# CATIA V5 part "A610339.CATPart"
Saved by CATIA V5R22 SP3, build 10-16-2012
Part number: D38999/26TH35PN
Revision: A
Definition: A610339
Nomenclature: CONNECTOR, ELEC, PLUG, CIRCULAR, THD, STR, REM CRP CONT
Source: bought
Description: CONNECTOR, ELEC, PLUG, CIRCULAR, THD, STR, REM CRP CONT
Publications: "Logical Termination.1", "Logical Pin.1", "CCP", "CCP_generated(CCP)", "Coincidence_generated(CCP)", "CCP Orientation_generated(CCP)", "BCP", "BCP_generated(BCP)", "Face_generated(BCP)", "BaCP", "BaCP_generated(BaCP)", "BaCP Orientation_generated(BaCP)"
Material "Density=.1010": density 2795.67 kg/m3
Bounding box of the stored display mesh (mm): x -33.16 to 0, y -22.264 to 22.264, z -22.43 to 22.43
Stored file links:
  C:\Users\u305772\OneDrive - Gulfstream Aerospace\AD PAG\Harness\A610339.CATPart
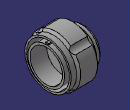
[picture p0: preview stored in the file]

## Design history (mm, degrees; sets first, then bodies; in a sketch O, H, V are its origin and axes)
Parameters
  PartNumber = "D38999/26TH35PN"
  OtherKeywords = "CONNECTORS, ELECTRICAL, PLUG, CIRCULAR, THREADED, STRAIGHT, REMOVABLE CRIMP CONTACTS SERIES III, METRIC"
  Comments = "DD THD: 1.5, VV THD: M34x1.0-6g 0.100R, NICKEL FLUOROCARBON POLYMER OVER A SUITABLE UNDERPLATE (CONDUCTIVE) -65 DEG C TO +175 DEG C, PIN"
  CAGECode = "96906"
  WeightComment = "CALCULATED FROM CATIA"
  WeightSource = "Calculated"
  Volume = 2.82225e-05 (volume) {= smartVolume(Body1)}
  Density = 2795.67 (density)
  Weight = 0.13638
AxisSystem1: origin (0, 0, 0), X (1, 0, 0), Y (0, 1, 0), Z (0, 0, 1)
Set1
  Point1 "CCP": type Center, Curve edge [face of Shaft1 from Sketch1.L2 | face of Shaft1 from Sketch1.L1]
  Point2 "BaCP": type Center, Curve edge [face of Shaft1 from Sketch1.L17 | face of Shaft1 from Sketch1.L16]
  Point3 "BCP": type Center, Curve edge [face of Shaft1 from Sketch1.L19 | face of Shaft1 from Sketch1.L18]
  Point4: (0, 0, 3.175), relative to Point1, in AxisSystem1
  Point5: (0, 0, 3.175), relative to Point2, in AxisSystem1
  Line1 "Coincidence": type PtPt, FirstPoint Point1, SecondPoint Point3
  Line2 "CCP Orientation": type PtPt, FirstPoint Point1, SecondPoint Point4
  Line3 "BaCP Orientation": type PtPt, FirstPoint Point2, SecondPoint Point5
Body1 (main body)
  Sketch1 on ZX plane of AxisSystem1, origin (0, 0, 0), H (1, 0, 0), V (0, 0, 1)
    point P1 (-14.565, 0)
    line L1 (-14.565, 0) -> (-14.565, 14.175)
    point P2 (-14.565, 14.175)
    line L2 (-14.565, 14.175) -> (-15.01, 14.175)
    point P3 (-15.01, 14.175)
    line L3 (-15.01, 14.175) -> (-15.01, 14.385)
    point P4 (-15.01, 14.385)
    line L4 (-15.01, 14.385) -> (0, 14.385)
    point P5 (0, 14.385)
    line L5 (0, 14.385) -> (0, 16.2575)
    point P6 (0, 16.2575)
    line L6 (0, 16.2575) -> (-15.01, 16.2575)
    point P7 (-15.01, 16.2575)
    line L7 (-15.01, 16.2575) -> (-15.01, 19.05)
    point P8 (-15.01, 19.05)
    line L8 (-15.01, 19.05) -> (-1.54, 19.05)
    point P9 (-1.54, 19.05)
    line L9 (-1.54, 19.05) -> (-1.54, 20.55)
    point P10 (-1.54, 20.55)
    line L10 (-1.54, 20.55) -> (-6.24, 20.55)
    point P11 (-6.24, 20.55)
    line L11 (-6.24, 20.55) -> (-8.14, 22.45)
    point P12 (-8.14, 22.45)
    line L12 (-8.14, 22.45) -> (-23, 22.45)
    point P13 (-23, 22.45)
    line L13 (-23, 22.45) -> (-23, 17)
    point P14 (-23, 17)
    line L14 (-23, 17) -> (-27.74, 17)
    point P15 (-27.74, 17)
    line L15 (-27.74, 17) -> (-28.46, 16.28)
    point P16 (-28.46, 16.28)
    line L16 (-28.46, 16.28) -> (-31, 16.28)
    point P17 (-31, 16.28)
    line L17 (-31, 16.28) -> (-31, 14.565)
    point P18 (-31, 14.565)
    line L18 (-31, 14.565) -> (-33.16, 14.565)
    point P19 (-33.16, 14.565)
    line L19 (-33.16, 14.565) -> (-33.16, 0)
    point P20 (-33.16, 0)
    axis line L20 (-33.16, 0) -> (-14.565, 0)
    point P21 (-14.565, -14.175)
    point P22 (-14.565, 0)
    construction line L21 (-14.565, 0) -> (-14.565, -14.175)
    point P23 (-15.01, -14.175)
    construction line L22 (-14.565, -14.175) -> (-15.01, -14.175)
    point P24 (-15.01, -14.385)
    construction line L23 (-15.01, -14.175) -> (-15.01, -14.385)
    point P25 (0, -14.385)
    construction line L24 (-15.01, -14.385) -> (0, -14.385)
    point P26 (0, -16.2575)
    construction line L25 (0, -14.385) -> (0, -16.2575)
    point P27 (-15.01, -16.2575)
    construction line L26 (0, -16.2575) -> (-15.01, -16.2575)
    point P28 (-15.01, -19.05)
    construction line L27 (-15.01, -16.2575) -> (-15.01, -19.05)
    point P29 (-1.54, -19.05)
    construction line L28 (-15.01, -19.05) -> (-1.54, -19.05)
    point P30 (-1.54, -20.55)
    construction line L29 (-1.54, -19.05) -> (-1.54, -20.55)
    point P31 (-6.24, -20.55)
    construction line L30 (-1.54, -20.55) -> (-6.24, -20.55)
    point P32 (-8.14, -22.45)
    construction line L31 (-6.24, -20.55) -> (-8.14, -22.45)
    point P33 (-23, -22.45)
    construction line L32 (-8.14, -22.45) -> (-23, -22.45)
    point P34 (-23, -17)
    construction line L33 (-23, -22.45) -> (-23, -17)
    point P35 (-27.74, -17)
    construction line L34 (-23, -17) -> (-27.74, -17)
    point P36 (-28.46, -16.28)
    construction line L35 (-27.74, -17) -> (-28.46, -16.28)
    point P37 (-31, -16.28)
    construction line L36 (-28.46, -16.28) -> (-31, -16.28)
    point P38 (-31, -14.565)
    construction line L37 (-31, -16.28) -> (-31, -14.565)
    point P39 (-33.16, -14.565)
    construction line L38 (-31, -14.565) -> (-33.16, -14.565)
    point P40 (-33.16, 0)
    construction line L39 (-33.16, -14.565) -> (-33.16, 0)
    distance L9 P11 = 4.7
    distance L10 L30 = 41.1
    distance L12 L32 = 44.9
    distance L5 L17 = 31
    distance L2 L22 = 28.35
    angle L16 L15 = 45
    angle L10 L11 = 45
    distance L5 L7 = 15.01
    distance L6 L26 = 32.515
    distance L24 L4 = 28.77
    distance L3 L1 = 0.445
    distance L8 L28 = 38.1
    distance L7 L9 = 13.47
    distance L17 L13 = 8
    distance L17 L19 = 2.16
    distance L38 L18 = 29.13
    distance L36 L16 = 32.56
    distance L34 L14 = 34
    distance L17 P16 = 2.54
    coincidence: P1 H, P5 V, P20 H, L7 L3
    vertical: L1 V, L3 V, L5 V, L7 V, L9 V, L13 V, L17 V, L19 V
    horizontal: L2 H, L4 H, L6 H, L8 H, L10 H, L12 H, L14 H, L16 H, L18 H, L20 H
    symmetry: P2 P21 L20, P1 P22 L20, L1 L21 L20, P3 P23 L20, L2 L22 L20, P4 P24 L20, L3 L23 L20, P5 P25 L20, L4 L24 L20, P6 P26 L20, L5 L25 L20, P7 P27 L20, L6 L26 L20, P8 P28 L20, L7 L27 L20, P9 P29 L20, L8 L28 L20, P10 P30 L20, L9 L29 L20, P11 P31 L20, L10 L30 L20, P12 P32 L20, L11 L31 L20, P13 P33 L20, L12 L32 L20, P14 P34 L20, L13 L33 L20, P15 P35 L20, L14 L34 L20, P16 P36 L20, L15 L35 L20, P17 P37 L20, L16 L36 L20, P18 P38 L20, L17 L37 L20, P19 P39 L20, L18 L38 L20, P20 P40 L20, L19 L39 L20
  Shaft1: profile Sketch1, axis Sketch1.L20, angle 360
  Sketch2 on face of Shaft1 from Sketch1.L5, origin (0, 0, 0), H (0, 1, 0), V (0, 0, 1)
    construction circle A1 centre (0, 0) radius 20.85
    construction line L1 (-20.85, 0) -> (20.85, 0)
    point P1 (-20.85, 0)
    point P2 (20.85, 0)
    arc A2 centre (17.8223, 17.8223) radius 4.3546 from (13.4699, 17.9601) to (17.9601, 13.4699) ccw
    arc A3 centre (0, 0) radius 22.45 from (17.9601, 13.4699) to (13.4699, 17.9601) ccw
    construction line L2 (0, 0) -> (17.8223, 17.8223)
    reference projected circle E1 centre (0, 0) radius 22.45 from edge [face of Shaft1 from Sketch1.L12 | face of Shaft1 from Sketch1.L11]
    point P4 (17.9601, 13.4699)
    point P5 (13.4699, 17.9601)
    length L1 = 41.7
    angle L1 L2 = 45
    distance P5 P4 = 6.35
    coincidence: P1 A1, P1 H, P2 A1
    horizontal: L1 H
    tangency: A2 A1, A3 E1
  Pocket1: profile Sketch2, direction (-1, 0, 0), through (limit type 6)
  CircPattern1: of Pocket1, instances 4, angular step 90, axis from face of Shaft1 from Sketch1.L9
  Sketch3 on face of Shaft1 from Sketch1.L5, origin (0, 0, 0), H (0, 1, 0), V (0, 0, 1)
    arc A1 centre (0, 0) radius 16.2575 from (1.27, 16.2078) to (-1.27, 16.2078) ccw
    line L1 (1.27, 17.2182) -> (1.27, 16.2078)
    line L2 (-1.27, 16.2078) -> (-1.27, 17.2182)
    point P1 (1.27, 16.2078)
    point P2 (-1.27, 16.2078)
    reference projected circle E1 centre (0, 0) radius 16.2575 from edge [face of Shaft1 from Sketch1.L6 | face of Shaft1 from Sketch1.L5]
    point P3 (-1.27, -16.2078)
    point P4 (1.27, -16.2078)
    construction arc A2 centre (0, 0) radius 16.2575 from (1.27, -16.2078) to (-1.27, -16.2078) cw
    construction line L3 (-1.27, -16.2078) -> (-1.27, -17.2182)
    construction line L4 (1.27, -17.2182) -> (1.27, -16.2078)
    arc A3 centre (0, 0) radius 17.265 from (1.27, 17.2182) to (-1.27, 17.2182) ccw
    point P6 (1.27, 17.2182)
    point P7 (-1.27, 17.2182)
    point P8 (-1.27, -17.2182)
    point P9 (1.27, -17.2182)
    construction arc A4 centre (0, 0) radius 17.265 from (1.27, -17.2182) to (-1.27, -17.2182) cw
    construction line L5 (0, 17.265) -> (0, -17.265)
    point P11 (0, 17.265)
    point P12 (0, -17.265)
    distance L2 L1 = 2.54
    length L5 = 34.53
    vertical: L1 V, L2 V, L5 V
    symmetry: L1 L2 V, P2 P3 H, P1 P4 H, A1 A2 H, L2 L3 H, L1 L4 H, P7 P8 H, P6 P9 H, A3 A4 H
    tangency: A1 E1
    coincidence: P11 A3, P11 V, P12 A4
  Pad1: profile Sketch3, direction (-1, 0, 0), length 7.24, opposite side length -0.76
